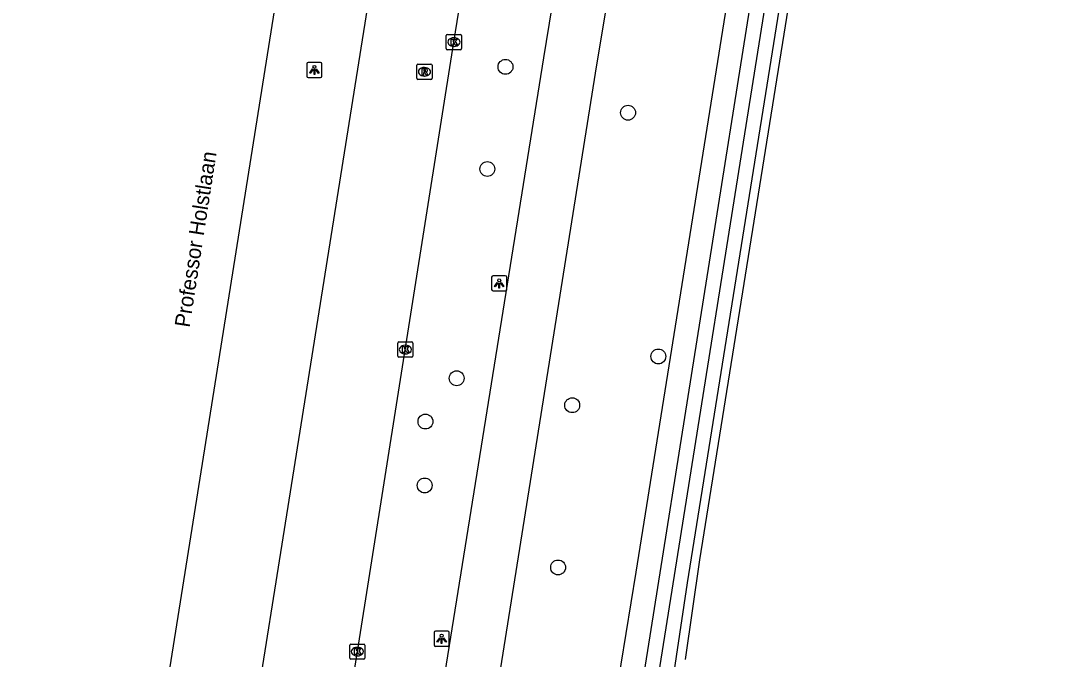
# Model space of a CAD drawing. Extents: x 160203 to 161526, y 379529 to 381797.
# Drawn here: x 160267 to 160334.7, y 380095.4 to 380137.4 of the extents above; entities that cross this region are included whole.
import ezdxf

# ---------------------------------------------------------------- set-up
doc = ezdxf.new("R2010")
doc.units = 0
for name, color, linetype in [('IMGEO_Boom', 7, 'Continuous'), ('IMGEO_Fietspad_gesloten', 7, 'Continuous'), ('IMGEO_Grasland_agrarisch', 7, 'Continuous'), ('IMGEO_Groenvoorziening', 7, 'Continuous'), ('IMGEO_Kolk', 7, 'Continuous'), ('IMGEO_Lichtpunt', 7, 'Continuous'), ('IMGEO_Loofbos', 7, 'Continuous'), ('IMGEO_Openbare_ruimte_label', 7, 'Continuous'), ('IMGEO_Rijbaan_regionaal_gesloten', 7, 'Continuous'), ('IMGEO_Rioolput', 7, 'Continuous'), ('IMGEO_Waterloop', 7, 'Continuous')]:
    doc.layers.add(name, color=color, linetype=linetype)

msp = doc.modelspace()

# ---------------------------------------------------------------- linework, layer by layer
at = {"layer": 'IMGEO_Boom'}
for centre in [(160298.933, 380134.399), (160306.996, 380131.382), (160297.739, 380127.682), (160308.99, 380115.357), (160295.721, 380113.926), (160303.32, 380112.154), (160293.668, 380111.081), (160293.615, 380106.877), (160302.395, 380101.488)]:
    msp.add_circle(centre, 0.489, dxfattribs=at)
at = {"layer": 'IMGEO_Fietspad_gesloten'}
for points in [[(160284.774, 380030.19), (160292.614, 380079.457), (160295.043, 380095.124), (160301.457, 380134.981), (160302.004, 380138.344)], [(160283.537, 380000), (160288.248, 380029.615), (160296.048, 380078.644), (160304.946, 380134.52), (160305.52, 380137.937)]]:
    msp.add_lwpolyline(points, dxfattribs=at)
at = {"layer": 'IMGEO_Grasland_agrarisch'}
msp.add_lwpolyline([(160334.717, 380245.43), (160311.69, 380101.979), (160310.75, 380095.431)], dxfattribs=at)
at = {"layer": 'IMGEO_Groenvoorziening'}
msp.add_lwpolyline([(160302.532, 380043.918), (160302.689, 380044.357), (160304.383, 380056.886), (160310.899, 380100.468), (160334.158, 380245.601)], dxfattribs=at)
at = {"layer": 'IMGEO_Kolk'}
for p, q in [((160295.039, 380135.6), (160295.039, 380136.452)), ((160295.114, 380136.526), (160295.966, 380136.526)), ((160295.527, 380136.306), (160295.552, 380136.306)), ((160296.04, 380136.452), (160296.04, 380135.6)), ((160295.966, 380135.526), (160295.114, 380135.526)), ((160295.55, 380135.746), (160295.525, 380135.746)), ((160291.846, 380115.386), (160291.846, 380116.238)), ((160291.921, 380116.312), (160292.773, 380116.312)), ((160292.334, 380116.092), (160292.359, 380116.092)), ((160292.847, 380116.238), (160292.847, 380115.386)), ((160292.773, 380115.312), (160291.921, 380115.312)), ((160292.357, 380115.532), (160292.332, 380115.532)), ((160288.687, 380095.53), (160288.687, 380096.382)), ((160288.762, 380096.456), (160289.614, 380096.456)), ((160289.175, 380096.236), (160289.2, 380096.236)), ((160289.688, 380096.382), (160289.688, 380095.53)), ((160289.198, 380095.676), (160289.173, 380095.676)), ((160289.614, 380095.456), (160288.762, 380095.456))]:
    msp.add_line(p, q, dxfattribs=at)
for points in [[(160295.039, 380135.6), (160295.039, 380136.452)], [(160295.114, 380136.526), (160295.966, 380136.526)], [(160295.36, 380136.226), (160295.483, 380136.226), (160295.483, 380136.075), (160295.613, 380136.226), (160295.777, 380136.226), (160295.631, 380136.075), (160295.784, 380135.826), (160295.632, 380135.826), (160295.547, 380135.99), (160295.483, 380135.923), (160295.483, 380135.826), (160295.36, 380135.826), (160295.36, 380136.226)], [(160296.04, 380136.452), (160296.04, 380135.6)], [(160295.966, 380135.526), (160295.114, 380135.526)], [(160291.846, 380115.386), (160291.846, 380116.238)], [(160291.921, 380116.312), (160292.773, 380116.312)], [(160292.167, 380116.012), (160292.29, 380116.012), (160292.29, 380115.861), (160292.42, 380116.012), (160292.584, 380116.012), (160292.438, 380115.861), (160292.591, 380115.612), (160292.439, 380115.612), (160292.354, 380115.776), (160292.29, 380115.709), (160292.29, 380115.612), (160292.167, 380115.612), (160292.167, 380116.012)], [(160292.847, 380116.238), (160292.847, 380115.386)], [(160292.773, 380115.312), (160291.921, 380115.312)], [(160288.687, 380095.53), (160288.687, 380096.382)], [(160288.762, 380096.456), (160289.614, 380096.456)], [(160289.008, 380096.156), (160289.131, 380096.156), (160289.131, 380096.005), (160289.261, 380096.156), (160289.425, 380096.156), (160289.279, 380096.005), (160289.432, 380095.756), (160289.28, 380095.756), (160289.195, 380095.92), (160289.131, 380095.853), (160289.131, 380095.756), (160289.008, 380095.756), (160289.008, 380096.156)], [(160289.688, 380096.382), (160289.688, 380095.53)], [(160289.614, 380095.456), (160288.762, 380095.456)]]:
    msp.add_lwpolyline(points, dxfattribs=at)
for centre, start, end in [((160295.116, 380136.45), 91.55205, 178.44795), ((160295.116, 380136.45), 91.55205, 178.44795), ((160295.964, 380136.45), 1.55205, 88.44795), ((160295.964, 380136.45), 1.55205, 88.44795), ((160295.116, 380135.602), 181.55205, 268.44795), ((160295.116, 380135.602), 181.55205, 268.44795), ((160295.964, 380135.602), 271.55205, 358.44795), ((160295.964, 380135.602), 271.55205, 358.44795), ((160291.923, 380116.236), 91.55205, 178.44795), ((160291.923, 380116.236), 91.55205, 178.44795), ((160292.771, 380116.236), 1.55205, 88.44795), ((160292.771, 380116.236), 1.55205, 88.44795), ((160291.923, 380115.388), 181.55205, 268.44795), ((160291.923, 380115.388), 181.55205, 268.44795), ((160292.771, 380115.388), 271.55205, 358.44795), ((160292.771, 380115.388), 271.55205, 358.44795), ((160288.764, 380096.38), 91.55205, 178.44795), ((160288.764, 380096.38), 91.55205, 178.44795), ((160289.612, 380096.38), 1.55205, 88.44795), ((160289.612, 380096.38), 1.55205, 88.44795), ((160288.764, 380095.532), 181.55205, 268.44795), ((160288.764, 380095.532), 181.55205, 268.44795), ((160289.612, 380095.532), 271.55205, 358.44795), ((160289.612, 380095.532), 271.55205, 358.44795)]:
    msp.add_arc(centre, 0.0765, start, end, dxfattribs=at)
for centre, major_axis, ratio, start_param, end_param in [((160295.526, 380136.026), (-0.387, 0.002), 0.722429, 4.712389, 7.853982), ((160295.551, 380136.026), (-0.39, 0.002), 0.717154, 1.570796, 4.712389), ((160292.333, 380115.812), (-0.387, 0.002), 0.722429, 4.712389, 7.853982), ((160292.358, 380115.812), (-0.39, 0.002), 0.717154, 1.570796, 4.712389), ((160289.174, 380095.956), (-0.387, 0.002), 0.722429, 4.712389, 7.853982), ((160289.199, 380095.956), (-0.39, 0.002), 0.717154, 1.570796, 4.712389)]:
    msp.add_ellipse(centre, major_axis=major_axis, ratio=ratio, start_param=start_param, end_param=end_param, dxfattribs=at)
at = {"layer": 'IMGEO_Lichtpunt'}
for p, q in [((160285.864, 380134.597), (160285.864, 380133.79)), ((160285.864, 380134.597), (160285.864, 380133.79)), ((160286.766, 380134.692), (160285.958, 380134.692)), ((160286.766, 380134.692), (160285.958, 380134.692)), ((160286.86, 380133.79), (160286.86, 380134.597)), ((160286.86, 380133.79), (160286.86, 380134.597)), ((160285.958, 380133.696), (160286.766, 380133.696)), ((160285.958, 380133.696), (160286.766, 380133.696)), ((160298.02, 380120.564), (160298.02, 380119.757)), ((160298.02, 380120.564), (160298.02, 380119.757)), ((160298.922, 380120.659), (160298.114, 380120.659)), ((160298.922, 380120.659), (160298.114, 380120.659)), ((160299.016, 380119.757), (160299.016, 380120.564)), ((160299.016, 380119.757), (160299.016, 380120.564)), ((160298.114, 380119.663), (160298.922, 380119.663)), ((160298.114, 380119.663), (160298.922, 380119.663)), ((160294.232, 380097.204), (160294.232, 380096.397)), ((160294.232, 380097.204), (160294.232, 380096.397)), ((160295.134, 380097.299), (160294.326, 380097.299)), ((160295.134, 380097.299), (160294.326, 380097.299)), ((160295.228, 380096.397), (160295.228, 380097.204)), ((160295.228, 380096.397), (160295.228, 380097.204)), ((160294.326, 380096.303), (160295.134, 380096.303)), ((160294.326, 380096.303), (160295.134, 380096.303))]:
    msp.add_line(p, q, dxfattribs=at)
for points in [[(160286.238, 380134.261), (160286.277, 380134.233), (160286.089, 380133.971), (160286.051, 380133.998), (160286.238, 380134.261)], [(160286.34, 380134.213), (160286.387, 380134.213), (160286.387, 380133.891), (160286.34, 380133.891), (160286.34, 380134.213)], [(160286.45, 380134.233), (160286.488, 380134.26), (160286.675, 380133.998), (160286.636, 380133.97), (160286.45, 380134.233)], [(160298.394, 380120.228), (160298.433, 380120.2), (160298.245, 380119.938), (160298.207, 380119.965), (160298.394, 380120.228)], [(160298.496, 380120.18), (160298.543, 380120.18), (160298.543, 380119.858), (160298.496, 380119.858), (160298.496, 380120.18)], [(160298.606, 380120.2), (160298.644, 380120.227), (160298.831, 380119.965), (160298.792, 380119.937), (160298.606, 380120.2)], [(160294.606, 380096.868), (160294.645, 380096.84), (160294.457, 380096.578), (160294.419, 380096.605), (160294.606, 380096.868)], [(160294.818, 380096.84), (160294.856, 380096.867), (160295.043, 380096.605), (160295.004, 380096.577), (160294.818, 380096.84)], [(160294.708, 380096.82), (160294.755, 380096.82), (160294.755, 380096.498), (160294.708, 380096.498), (160294.708, 380096.82)]]:
    msp.add_lwpolyline(points, dxfattribs=at)
for centre in [(160286.363, 380134.395), (160298.519, 380120.362), (160294.731, 380097.002)]:
    msp.add_circle(centre, 0.0994, dxfattribs=at)
for centre, start, end in [((160285.958, 380134.597), 90, 180), ((160285.958, 380134.597), 90, 180), ((160286.766, 380134.597), 0, 90), ((160286.766, 380134.597), 0, 90), ((160285.958, 380133.79), 180, 270), ((160285.958, 380133.79), 180, 270), ((160286.766, 380133.79), 270, 0), ((160286.766, 380133.79), 270, 360), ((160298.114, 380120.564), 90, 180), ((160298.114, 380120.564), 90, 180), ((160298.922, 380120.564), 0, 90), ((160298.922, 380120.564), 0, 90), ((160298.114, 380119.757), 180, 270), ((160298.114, 380119.757), 180, 270), ((160298.922, 380119.757), 270, 0), ((160298.922, 380119.757), 270, 360), ((160294.326, 380097.204), 90, 180), ((160294.326, 380097.204), 90, 180), ((160295.134, 380097.204), 0, 90), ((160295.134, 380097.204), 0, 90), ((160294.326, 380096.397), 180, 270), ((160294.326, 380096.397), 180, 270), ((160295.134, 380096.397), 270, 0), ((160295.134, 380096.397), 270, 360)]:
    msp.add_arc(centre, 0.0946, start, end, dxfattribs=at)
at = {"layer": 'IMGEO_Loofbos'}
msp.add_lwpolyline([(160329.392, 380237.954), (160307.502, 380101.169), (160298.952, 380048.758)], dxfattribs=at)
at = {"layer": 'IMGEO_Rijbaan_regionaal_gesloten'}
for points in [[(160278.866, 380031.167), (160280.089, 380038.807), (160283.219, 380058.699), (160286.512, 380079.426), (160289.187, 380095.956), (160295.539, 380136.026), (160298.793, 380156.267), (160302.317, 380178.493), (160305.54, 380198.747), (160308.625, 380217.982), (160311.861, 380238.211), (160313.74, 380250), (160314.354, 380253.856), (160314.593, 380255.474), (160319.718, 380287.464)], [(160267.031, 380033.123), (160271.433, 380060.799), (160283.582, 380137.115), (160290.485, 380180.229), (160301.592, 380250), (160302.082, 380253.08)], [(160306.488, 380242.671), (160296.399, 380179.3), (160289.509, 380136.181), (160277.333, 380059.825), (160272.928, 380032.148)]]:
    msp.add_lwpolyline(points, dxfattribs=at)
at = {"layer": 'IMGEO_Rioolput'}
for p, q in [((160293.101, 380133.648), (160293.101, 380134.5)), ((160293.176, 380134.574), (160294.028, 380134.574)), ((160293.589, 380134.354), (160293.614, 380134.354)), ((160294.102, 380134.5), (160294.102, 380133.648)), ((160294.028, 380133.574), (160293.176, 380133.574)), ((160293.612, 380133.794), (160293.587, 380133.794))]:
    msp.add_line(p, q, dxfattribs=at)
for points in [[(160293.101, 380133.648), (160293.101, 380134.5)], [(160293.176, 380134.574), (160294.028, 380134.574)], [(160293.69, 380134.272), (160293.438, 380134.274), (160293.438, 380133.874)], [(160293.616, 380134.193), (160293.562, 380134.193), (160293.562, 380134.112)], [(160293.562, 380134.112), (160293.614, 380134.112)], [(160294.102, 380134.5), (160294.102, 380133.648)], [(160294.028, 380133.574), (160293.176, 380133.574)], [(160293.438, 380133.874), (160293.562, 380133.874), (160293.562, 380134.036), (160293.573, 380134.036)], [(160293.62, 380134.007), (160293.691, 380133.874), (160293.831, 380133.874), (160293.766, 380134)]]:
    msp.add_lwpolyline(points, dxfattribs=at)
for centre, radius, start, end in [((160293.178, 380134.498), 0.0765, 91.55205, 178.44795), ((160293.178, 380134.498), 0.0765, 91.55205, 178.44795), ((160293.598, 380134.301), 0.19, 274.7715, 282.96867), ((160293.622, 380134.097), 0.0964, 77.00612, 93.18647), ((160293.636, 380134.154), 0.0378, 276.66336, 79.67722), ((160293.689, 380134.162), 0.109, 350.36119, 89.41601), ((160293.687, 380134.162), 0.112, 277.58423, 350.98172), ((160294.026, 380134.498), 0.0765, 1.55205, 88.44795), ((160294.026, 380134.498), 0.0765, 1.55205, 88.44795), ((160293.178, 380133.65), 0.0765, 181.55205, 268.44795), ((160293.178, 380133.65), 0.0765, 181.55205, 268.44795), ((160293.572, 380133.983), 0.0533, 26.02933, 88.69889), ((160293.671, 380133.947), 0.108, 29.51342, 73.79051), ((160294.026, 380133.65), 0.0765, 271.55205, 358.44795), ((160294.026, 380133.65), 0.0765, 271.55205, 358.44795)]:
    msp.add_arc(centre, radius, start, end, dxfattribs=at)
for centre, major_axis, ratio, start_param, end_param in [((160293.588, 380134.074), (-0.387, 0.002), 0.722429, 4.712389, 7.853982), ((160293.613, 380134.074), (-0.39, 0.002), 0.717154, 1.570796, 4.712389)]:
    msp.add_ellipse(centre, major_axis=major_axis, ratio=ratio, start_param=start_param, end_param=end_param, dxfattribs=at)
at = {"layer": 'IMGEO_Waterloop'}
msp.add_lwpolyline([(160326.146, 380202.356), (160331.264, 380234.48), (160332.922, 380245.296), (160332.525, 380245.357), (160331.949, 380245.446), (160330.291, 380234.632), (160325.173, 380202.511), (160324.329, 380197.004), (160315.588, 380142.012), (160307.904, 380093.679), (160300.044, 380045.549), (160300.116, 380045.227), (160300.306, 380045.1), (160300.596, 380045.1), (160300.813, 380045.163), (160301.016, 380045.39), (160308.876, 380093.522), (160316.56, 380141.858), (160325.302, 380196.852), (160326.146, 380202.356)], dxfattribs=at)

# ---------------------------------------------------------------- texts
at = {"layer": 'IMGEO_Openbare_ruimte_label'}
msp.add_text('Professor Holstlaan', height=1, rotation=81.1972, dxfattribs=at).set_placement((160278.145, 380117.226))

doc.saveas('drawing.dxf')
